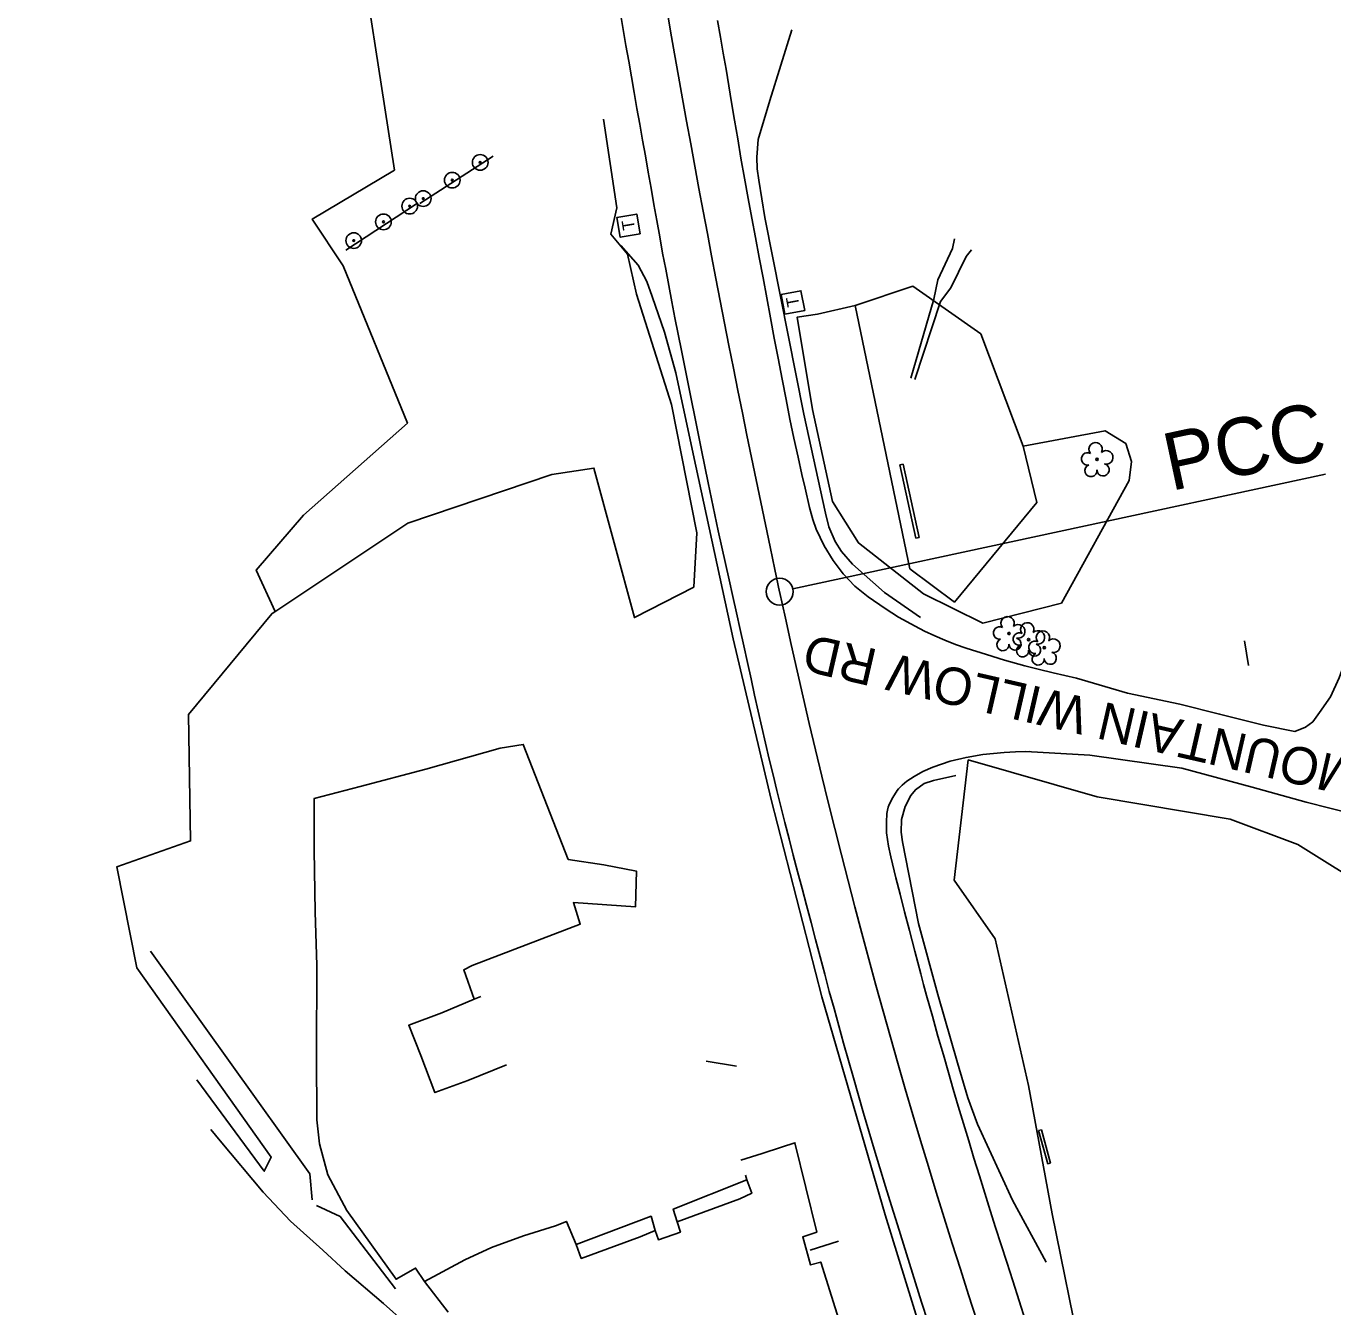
# Model space of a CAD drawing. Extents: x 477009 to 479892, y 492858 to 496862.
# Drawn here: x 478243.9 to 478607.7, y 494829.6 to 495186.3 of the extents above; entities that cross this region are included whole.
import ezdxf

# ---------------------------------------------------------------- set-up
doc = ezdxf.new("R2010")
doc.units = 0
for name, color, linetype in [('Exist Guardrail', 7, 'Continuous'), ('Exist Horizontal Alignment', 7, 'Continuous'), ('Exist Other Culture Area Outline', 7, 'Continuous'), ('Exist Other Culture Fence Line', 7, 'Continuous'), ('Exist Other Culture Gate', 7, 'Continuous'), ('Exist Other Culture Sign', 7, 'Continuous'), ('Exist Other Culture Sign Post CELL', 7, 'Continuous'), ('Exist Roads EOP', 7, 'Continuous'), ('Exist Roads EOP Other', 7, 'Continuous'), ('Exist Roads EOP Text', 7, 'Continuous'), ('Exist Roads Soil', 7, 'Continuous'), ('Exist Structure Minor Head and End Wall', 7, 'Continuous'), ('Exist Utilities Telephone Pedestal CELL', 7, 'Continuous'), ('Exist Vegetation Hedge Row', 7, 'Continuous'), ('Exist Vegetation Tree CELL', 7, 'Continuous'), ('Exist Vegetation Woods Line', 7, 'Continuous')]:
    doc.layers.add(name, color=color, linetype=linetype)

msp = doc.modelspace()

# ---------------------------------------------------------------- linework, layer by layer
at = {"layer": 'Exist Guardrail'}
msp.add_line((478414.31, 495119.71), (478409.44, 495125.16), dxfattribs=at)
for points in [[(478457.07, 495185.25), (478450.97, 495165.58), (478447.7, 495154.68), (478447.3, 495149.78), (478447.4, 495146.51), (478447.84, 495143.4), (478449.58, 495132.98)], [(478449.58, 495132.98), (478460.43, 495078.23), (478466.42, 495050.59), (478467.33, 495046.8), (478469.09, 495042.72), (478470.88, 495039.94), (478473.91, 495036.4), (478482.86, 495028.58), (478492.88, 495021.57)], [(478500.17, 494799.65), (478483.05, 494855.25), (478465.43, 494915.92), (478451.3, 494970.92), (478440.7, 495015.6), (478429.63, 495067.15), (478424.79, 495089.7), (478421.62, 495101.03), (478418.13, 495110.93), (478416.73, 495115.1), (478414.31, 495119.71)], [(478502.7, 494977.59), (478496.47, 494976.2), (478493.94, 494975.37), (478491.47, 494973.6), (478490.17, 494972.02), (478488.57, 494968.95), (478487.63, 494965.36), (478487.46, 494961.78), (478487.86, 494959.13), (478492.31, 494936.39), (478497.73, 494916.63), (478503.16, 494897.57), (478506.02, 494887.82), (478508.75, 494880.48), (478518.53, 494859.34), (478527.84, 494842.05)]]:
    msp.add_lwpolyline(points, dxfattribs=at)
at = {"layer": 'Exist Horizontal Alignment'}
msp.add_line((478457.32, 495029.57), (478605.66, 495061.46), dxfattribs=at)
msp.add_circle((478453.66, 495028.78), 3.75, dxfattribs=at)
for centre, radius, start, end in [((482394.4, 495875.96), 4030.78, 189.24053, 192.1328), ((480407.9, 495448.91), 1998.89, 192.1328, 219.63873)]:
    msp.add_arc(centre, radius, start, end, dxfattribs=at)
at = {"layer": 'Exist Other Culture Area Outline'}
for points in [[(478377.65, 494897.05), (478366.82, 494892.7), (478357.67, 494889.29), (478353.75, 494899.67), (478350.41, 494908.07), (478359.63, 494911.55), (478368.63, 494915.35), (478370.45, 494916.06)], [(478397.05, 494847.04), (478417.87, 494854.86), (478419, 494850.88), (478419.92, 494848.3), (478426.03, 494850.44), (478425.12, 494853.29), (478424.02, 494856.85), (478444.53, 494865.01)]]:
    msp.add_lwpolyline(points, dxfattribs=at)
at = {"layer": 'Exist Other Culture Fence Line'}
for p, q in [((478322.88, 494866.69), (478278.52, 494928.65)), ((478346.73, 494834.69), (478331.3, 494854.79))]:
    msp.add_line(p, q, dxfattribs=at)
at = {"layer": 'Exist Other Culture Gate'}
for p, q in [((478323.55, 494859.43), (478322.88, 494866.69)), ((478331.3, 494854.79), (478324.68, 494857.84))]:
    msp.add_line(p, q, dxfattribs=at)
at = {"layer": 'Exist Other Culture Sign'}
for p, q in [((478373.94, 495150), (478353.53, 495136.88)), ((478352.6, 495136.74), (478332.89, 495123.88)), ((478583.05, 495015.08), (478584.23, 495008.22)), ((478441.63, 494896.67), (478433.17, 494898.08)), ((478462.18, 494845.43), (478470, 494847.92))]:
    msp.add_line(p, q, dxfattribs=at)
at = {"layer": 'Exist Other Culture Sign Post CELL'}
for centre, radius in [((478370.29, 495148.3), 2.18), ((478370.29, 495148.3), 0.24), ((478362.51, 495143.36), 2.18), ((478354.43, 495138.24), 2.18), ((478362.51, 495143.36), 0.24), ((478350.67, 495136.13), 2.18), ((478354.43, 495138.24), 0.24), ((478343.37, 495131.75), 2.18), ((478350.67, 495136.13), 0.24), ((478343.37, 495131.75), 0.24), ((478335.1, 495126.53), 2.18), ((478335.1, 495126.53), 0.24)]:
    msp.add_circle(centre, radius, dxfattribs=at)
at = {"layer": 'Exist Roads EOP'}
for points in [[(478494.88, 494825.53), (478493.16, 494830.92), (478491.46, 494836.31), (478489.78, 494841.7), (478488.11, 494847.09), (478486.45, 494852.45), (478484.81, 494857.79), (478483.17, 494863.11), (478481.57, 494868.37), (478480.01, 494873.53), (478478.5, 494878.6), (478477.04, 494883.57), (478475.62, 494888.48), (478474.21, 494893.36), (478472.83, 494898.21), (478471.46, 494903.04), (478470.12, 494907.86), (478468.8, 494912.67), (478467.49, 494917.49), (478466.21, 494922.31), (478464.93, 494927.11), (478463.66, 494931.91), (478462.4, 494936.68), (478461.14, 494941.44), (478459.89, 494946.16), (478458.67, 494950.83), (478457.46, 494955.44), (478456.27, 494959.99), (478455.11, 494964.5), (478453.98, 494968.97), (478452.89, 494973.39), (478451.82, 494977.78), (478450.78, 494982.16), (478449.75, 494986.57), (478448.73, 494991.01), (478447.71, 494995.49), (478446.7, 495000), (478445.7, 495004.53), (478444.69, 495009.08), (478443.69, 495013.65), (478442.68, 495018.24), (478441.67, 495022.84), (478440.64, 495027.45), (478439.6, 495032.07), (478438.57, 495036.66), (478437.57, 495041.21), (478436.58, 495045.72), (478435.62, 495050.17), (478434.68, 495054.62), (478433.74, 495059.11), (478432.81, 495063.64), (478431.89, 495068.21), (478430.97, 495072.81), (478430.05, 495077.42), (478429.11, 495082.04), (478428.17, 495086.68), (478427.23, 495091.3), (478426.31, 495095.9), (478425.4, 495100.47), (478424.51, 495105), (478423.64, 495109.52), (478422.78, 495114.04), (478421.93, 495118.55), (478421.09, 495123.07), (478420.27, 495127.58), (478419.46, 495132.1), (478418.65, 495136.61), (478417.86, 495141.13), (478417.07, 495145.63), (478416.28, 495150.1), (478415.5, 495154.54), (478414.71, 495158.95), (478413.94, 495163.34), (478413.16, 495167.73), (478412.4, 495172.11), (478411.63, 495176.49), (478410.88, 495180.87), (478410.13, 495185.29), (478409.39, 495189.74)], [(478436.39, 495187.86), (478437.19, 495183.22), (478437.96, 495178.73), (478438.73, 495174.23), (478439.51, 495169.66), (478440.3, 495164.98), (478441.11, 495160.09), (478441.98, 495154.89), (478442.9, 495149.47), (478443.87, 495143.89), (478444.88, 495138.3), (478445.91, 495132.82), (478446.96, 495127.36), (478448, 495121.8), (478449.04, 495116.2), (478450.07, 495110.6), (478451.1, 495105), (478452.16, 495099.41), (478453.24, 495093.75), (478454.36, 495087.97), (478455.47, 495082.26), (478456.54, 495076.84), (478457.63, 495071.55), (478458.78, 495066.23), (478459.86, 495061.4), (478460.73, 495057.58), (478462, 495052.18), (478462.87, 495048.83), (478463.82, 495046.17), (478466.08, 495041.55), (478468.54, 495037.5), (478471.31, 495033.78), (478474.55, 495030.3), (478478.26, 495027.37), (478483.01, 495024.06), (478486.75, 495021.7), (478491.36, 495019.15), (478494.02, 495017.8), (478496.82, 495016.47), (478499.68, 495015.24), (478502.6, 495014.11), (478505.58, 495013.08), (478511.25, 495011.25), (478516.22, 495009.72), (478521.94, 495008.15), (478525.61, 495007.21), (478529.83, 495006.19)], [(478629.94, 494979.48), (478627.56, 494984.41), (478625.78, 494990.88), (478625.05, 494995.74), (478625.3, 495001.86), (478625.45, 495008.65), (478623.44, 495009.56), (478621.4, 495011.06), (478619.18, 495012.42), (478617.88, 495012.45), (478616.24, 495012.81), (478614.17, 495012.38), (478611.75, 495011.2), (478609.42, 495004.8), (478607.05, 494999.52), (478603.97, 494995.11), (478602.1, 494992.54), (478600.1, 494991.08), (478597.12, 494989.88)], [(478529.83, 495006.19), (478536.26, 495004.68), (478550.46, 495000.51), (478565.08, 494997.44), (478576.14, 494994.68), (478588.38, 494991.56), (478597.12, 494989.88)], [(478522.13, 494825.76), (478520.32, 494831.34), (478518.54, 494836.87), (478516.87, 494842.07), (478515.31, 494846.92), (478513.8, 494851.71), (478512.3, 494856.5), (478510.79, 494861.32), (478509.26, 494866.16), (478507.76, 494871), (478506.29, 494875.85), (478504.82, 494880.71), (478503.37, 494885.56), (478501.99, 494890.28), (478500.67, 494894.9), (478499.25, 494899.8), (478497.73, 494905.02), (478496.17, 494910.54), (478495.37, 494913.41), (478494.57, 494916.34), (478493.75, 494919.35), (478492.94, 494922.41), (478492.11, 494925.55), (478491.31, 494928.64), (478489.81, 494934.39), (478488.45, 494939.61), (478487.18, 494944.52), (478486, 494949.12), (478484.63, 494954.94), (478484.01, 494957.92), (478483.43, 494961.63), (478483.37, 494964.61), (478483.52, 494966.99), (478483.67, 494967.93), (478483.89, 494968.77), (478484.19, 494969.56), (478485.16, 494971.44), (478486.39, 494973.41), (478486.74, 494973.86), (478487.73, 494974.86), (478489.11, 494976.01), (478491.07, 494977.3), (478493.56, 494978.7), (478496.28, 494979.94), (478501.11, 494981.55), (478505.55, 494982.61), (478510.23, 494983.48), (478516.19, 494984.03), (478519.36, 494984.18), (478523.2, 494984.25)], [(478743.38, 494949.64), (478742.27, 494949.53), (478730.99, 494949.01), (478720.81, 494949.18), (478712.04, 494949.22), (478703.75, 494949.86), (478694.98, 494950.85), (478685.03, 494952.07), (478676.02, 494953.93), (478665.98, 494956.24), (478654.46, 494958.66), (478644.79, 494960.89), (478639.88, 494961.57), (478637.6, 494962.06), (478613.38, 494966.78), (478600.21, 494970.17), (478585.19, 494974.37), (478565.6, 494979.6), (478540, 494983.26), (478522.21, 494984.28)]]:
    msp.add_lwpolyline(points, dxfattribs=at)
at = {"layer": 'Exist Roads EOP Other'}
for points in [[(478502.33, 495127.02), (478501.77, 495124.32), (478497.7, 495115.6), (478496.56, 495110.2), (478490.17, 495088.26)], [(478507.09, 495123.98), (478505.6, 495122.13), (478501.28, 495113.39), (478498.43, 495109.53), (478491.31, 495087.84)], [(478442.83, 494870.47), (478448.78, 494872.36), (478454.14, 494874.09), (478457.92, 494875.34), (478463.97, 494850.47), (478460.1, 494849.11), (478462.28, 494841.33), (478465.11, 494842.11), (478472.08, 494819.85)], [(478425.12, 494853.29), (478442.6, 494859.67), (478445.9, 494861.26), (478444.53, 494865.01), (478444.11, 494866.28)], [(478361.4, 494828.15), (478354.8, 494836.73), (478366.02, 494842.77), (478373.46, 494846.15), (478382.35, 494849.44), (478391.3, 494852.16), (478394.31, 494853.41), (478397.05, 494847.04), (478398.42, 494843.12), (478414.8, 494849.12), (478419, 494850.88)]]:
    msp.add_lwpolyline(points, dxfattribs=at)
at = {"layer": 'Exist Roads Soil'}
for points in [[(478354.8, 494836.73), (478352.32, 494840.43), (478346.87, 494837.3), (478333.17, 494856.42), (478327.9, 494866.39), (478325.57, 494875.03), (478324.85, 494881.7), (478324.73, 494899.99), (478324.77, 494924.69), (478324.37, 494939.6), (478324.08, 494956.78), (478324.04, 494971.15), (478336.88, 494974.55), (478355.13, 494979.39), (478375.81, 494985.24), (478382.27, 494986.24), (478394.8, 494954.22), (478404.75, 494952.7), (478413.8, 494950.98), (478413.57, 494941.04), (478396.25, 494942.21), (478398.15, 494936.21), (478368.1, 494924.65), (478365.7, 494923.52), (478368.63, 494915.35)], [(478467.21, 494726.56), (478464.83, 494726.17), (478461.66, 494727.06), (478457.64, 494729.35), (478447.95, 494735.74), (478435.81, 494744.3), (478418.94, 494757.57), (478409.61, 494766.39), (478399.97, 494775.08), (478389.28, 494784.63), (478378.01, 494796.26), (478369.6, 494805.03), (478358.27, 494817.2), (478349.43, 494825.17), (478343.4, 494830.55), (478332.71, 494839.64), (478326.48, 494845.44), (478317.52, 494853.54), (478309.86, 494861.57), (478297.91, 494875.85), (478295.31, 494879.06)]]:
    msp.add_lwpolyline(points, dxfattribs=at)
at = {"layer": 'Exist Structure Minor Head and End Wall'}
for p, q in [((478488.08, 495064.31), (478487.11, 495064.1)), ((478487.11, 495064.1), (478491.53, 495043.67)), ((478488.08, 495064.31), (478492.5, 495043.88)), ((478492.5, 495043.88), (478491.53, 495043.67)), ((478525.74, 494878.71), (478526.55, 494878.93)), ((478528.29, 494869.47), (478525.74, 494878.71)), ((478529.1, 494869.69), (478526.55, 494878.93)), ((478528.29, 494869.47), (478529.1, 494869.69))]:
    msp.add_line(p, q, dxfattribs=at)
at = {"layer": 'Exist Utilities Telephone Pedestal CELL'}
for p, q in [((478411.58, 495130.61), (478411.58, 495130.61)), ((478457.35, 495109.25), (478457.35, 495109.25))]:
    msp.add_line(p, q, dxfattribs=at)
for points in [[(478414.81, 495128.39), (478413.89, 495133.9), (478408.38, 495132.98), (478409.3, 495127.47), (478414.81, 495128.39)], [(478460.63, 495107.09), (478459.6, 495112.59), (478454.1, 495111.56), (478455.13, 495106.06), (478460.63, 495107.09)]]:
    msp.add_lwpolyline(points, dxfattribs=at)
at = {"layer": 'Exist Vegetation Hedge Row'}
for points in [[(478404.59, 495160.38), (478408.36, 495135.64), (478406.7, 495128.34), (478411.31, 495122.8), (478413.85, 495111.66), (478423.57, 495080.91), (478430.65, 495045.18), (478429.8, 495030.07), (478413.24, 495021.55), (478401.96, 495063.19), (478390.25, 495061.37), (478350.11, 495047.81), (478312.28, 495022.62)], [(478521.46, 495069.32), (478544.24, 495073.58), (478550.03, 495070.03), (478551.59, 495065.06), (478550.99, 495059.76), (478532.11, 495025.62), (478510.2, 495020.05), (478493.71, 495028.18), (478475.63, 495042.35), (478468.4, 495053.92), (478462.78, 495079.54), (478458.55, 495105.24), (478464.23, 495106.07), (478474.64, 495108.49)]]:
    msp.add_lwpolyline(points, dxfattribs=at)
at = {"layer": 'Exist Vegetation Tree CELL'}
for p, q in [((478542.02, 495065.6), (478542.02, 495065.6)), ((478517.5, 495017.13), (478517.5, 495017.13)), ((478522.98, 495015.42), (478522.98, 495015.42)), ((478527.33, 495013.14), (478527.33, 495013.14))]:
    msp.add_line(p, q, dxfattribs=at)
for centre in [(478542.02, 495065.6), (478517.5, 495017.13), (478522.98, 495015.42), (478527.33, 495013.14)]:
    msp.add_circle(centre, 0.326, dxfattribs=at)
for centre, radius, start, end in [((478541.64, 495068.47), 1.86, 330.1651, 219.7134), ((478544.57, 495066.19), 1.9, 257.1011, 134.1999), ((478539.42, 495065.75), 1.73, 62.6636, 279.3457), ((478540.32, 495062.48), 1.69, 111.5671, 6.231), ((478543.69, 495062.7), 1.7, 181.2822, 74.56), ((478517.12, 495020), 1.86, 330.1651, 219.7134), ((478514.9, 495017.28), 1.73, 62.6636, 279.3457), ((478520.38, 495015.57), 1.73, 62.6636, 279.3457), ((478520.05, 495017.71), 1.9, 257.1011, 134.1999), ((478522.6, 495018.29), 1.86, 330.1651, 219.7134), ((478525.53, 495016.01), 1.9, 257.1011, 134.1999), ((478526.95, 495016.02), 1.86, 330.1651, 219.7134), ((478515.8, 495014.01), 1.69, 111.5671, 6.231), ((478519.18, 495014.23), 1.7, 181.2822, 74.56), ((478521.28, 495012.3), 1.69, 111.5671, 6.231), ((478524.65, 495012.52), 1.7, 181.2822, 74.56), ((478524.72, 495013.3), 1.73, 62.6636, 279.3457), ((478529.88, 495013.73), 1.9, 257.1011, 134.1999), ((478525.63, 495010.02), 1.69, 111.5671, 6.231), ((478529, 495010.25), 1.7, 181.2822, 74.56)]:
    msp.add_arc(centre, radius, start, end, dxfattribs=at)
at = {"layer": 'Exist Vegetation Woods Line'}
for points in [[(478243.88, 495609.04), (478259.87, 495555.11), (478280.1, 495475.88), (478304.88, 495392.52), (478319.11, 495324.69), (478334.86, 495221.02), (478346.46, 495146.16), (478323.55, 495132.51), (478332.16, 495119.51)], [(478332.16, 495119.51), (478350.02, 495075.73), (478321.13, 495050.07), (478307.91, 495034.77), (478313.17, 495023.25), (478312.28, 495022.62), (478289.11, 494994.54), (478289.67, 494959.36), (478269.15, 494952.18), (478274.72, 494924), (478312.11, 494871.33), (478310.19, 494867.41), (478291.38, 494892.83)], [(478489.94, 495035.18), (478474.64, 495108.49), (478490.71, 495113.8), (478509.63, 495100.56), (478521.46, 495069.32), (478525.28, 495053.62), (478502.33, 495025.87), (478489.94, 495035.18)], [(478600.77, 494655.77), (478537.83, 494814.9), (478529.49, 494855.57), (478522.9, 494891.27), (478513.67, 494932.14), (478502.27, 494948.41), (478506.17, 494981.91), (478542.06, 494971.66), (478579.08, 494965.45), (478597.9, 494958.41), (478639.68, 494932.31), (478676.75, 494907.68), (478715.88, 494902.24), (478761.3, 494897.54)]]:
    msp.add_lwpolyline(points, dxfattribs=at)

# ---------------------------------------------------------------- texts
at = {"layer": 'Exist Horizontal Alignment'}
msp.add_text('PCC', height=16, rotation=12.1328, dxfattribs=at).set_placement((478562.56, 495056.77))
at = {"layer": 'Exist Roads EOP Text'}
msp.add_text('MOUNTAIN WILLOW RD ', height=10.4, rotation=167.061, dxfattribs=at).set_placement((478616.15, 494981.57))
at = {"layer": 'Exist Utilities Telephone Pedestal CELL'}
for rotation, p in [(99.463, (478413.45, 495129.78)), (100.645, (478459.24, 495108.45))]:
    msp.add_text('T', height=3.42, rotation=rotation, dxfattribs=at).set_placement(p)

doc.saveas('drawing.dxf')
